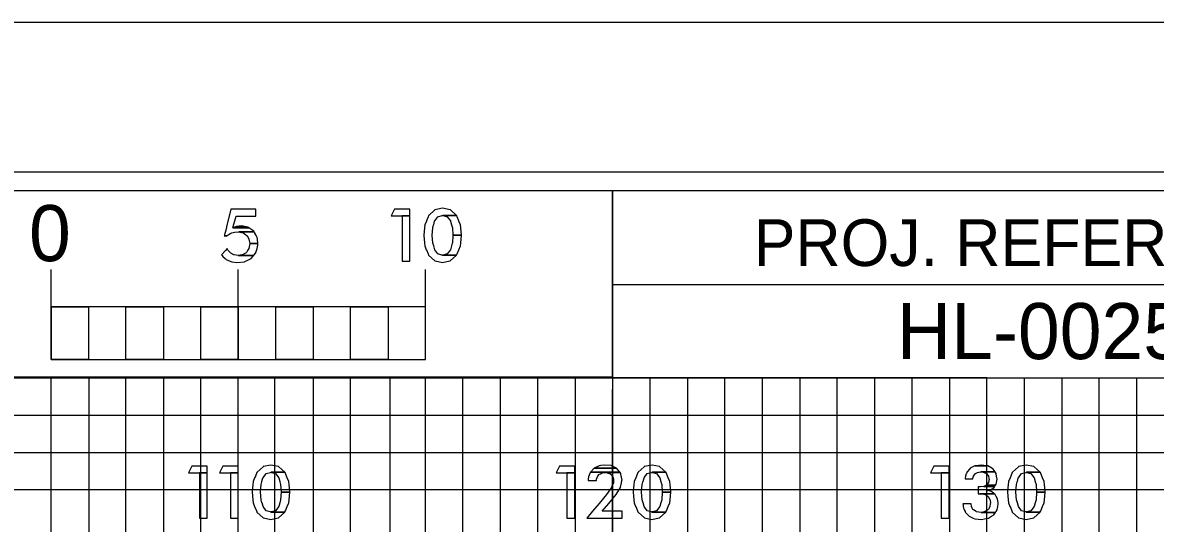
# Model space of a CAD drawing. Extents: x -13 to 323, y -5 to 1431.
# Drawn here: x 264.24 to 294.5, y 1081.11 to 1094.5 of the extents above; entities that cross this region are included whole.
import ezdxf

# ---------------------------------------------------------------- set-up
doc = ezdxf.new("R2010")
doc.units = 0
for name, color, linetype in [('Prop XS Bar Scale Labels', 7, 'Continuous'), ('Prop XS Offset Labels', 7, 'Continuous'), ('Prop XS Project Number', 7, 'Continuous'), ('Sheet Cross Section CELL', 7, 'Continuous'), ('Sheet Cross Section Grid Major CELL', 7, 'Continuous'), ('Sheet Cross Section Grid Middle CELL', 7, 'Continuous'), ('Sheet Cross Section Grid Minor 1 CELL', 7, 'Continuous'), ('Sheet Cross Section Grid Minor 2 CELL', 7, 'Continuous'), ('Sheet Cross Section Scale CELL', 7, 'Continuous'), ('Sheet Cutting Line CELL', 7, 'Continuous'), ('Sheet DOT Grid CELL', 7, 'Continuous'), ('Sheet Plot Border Inside CELL', 7, 'Continuous'), ('Sheet Plot Border Outside CELL', 7, 'Continuous')]:
    doc.layers.add(name, color=color, linetype=linetype)

msp = doc.modelspace()

# ---------------------------------------------------------------- linework, layer by layer
at = {"layer": 'Prop XS Bar Scale Labels'}
for points in [[(269.63, 1088.81), (269.627, 1088.798), (269.698, 1088.798), (269.711, 1088.81), (269.727, 1088.824), (269.798, 1088.867), (269.83, 1088.877), (269.9, 1088.899), (270.014, 1088.905), (270.422, 1088.905), (270.414, 1088.92), (270.28, 1089.015), (269.858, 1089.015), (269.861, 1089.028), (269.861, 1089.028), (269.866, 1089.048), (269.941, 1089.326), (270.466, 1089.326), (270.466, 1089.511), (269.803, 1089.511), (269.757, 1089.326), (269.689, 1089.048), (269.684, 1089.028), (269.681, 1089.015), (269.658, 1088.92), (269.654, 1088.905), (269.652, 1088.899), (269.647, 1088.877), (269.644, 1088.867), (269.634, 1088.824)], [(274.174, 1089.511), (274.085, 1089.329), (274.583, 1089.329), (274.583, 1089.511)], [(275.258, 1088.125), (275.457, 1088.084), (275.652, 1088.125), (275.663, 1088.127), (275.828, 1088.279), (275.454, 1088.279), (275.445, 1088.281), (275.44, 1088.283), (275.335, 1088.312), (275.248, 1088.425), (275.248, 1088.426), (275.248, 1088.426), (275.22, 1088.527), (275.22, 1088.529), (275.2, 1088.602), (275.198, 1088.606), (275.181, 1088.809), (275.181, 1088.811), (275.181, 1088.813), (275.198, 1089.015), (275.219, 1089.092), (275.22, 1089.094), (275.246, 1089.192), (275.247, 1089.195), (275.335, 1089.31), (275.448, 1089.339), (275.452, 1089.34), (275.462, 1089.343), (275.832, 1089.343), (275.669, 1089.492), (275.66, 1089.494), (275.46, 1089.538), (275.46, 1089.538), (275.252, 1089.494), (275.25, 1089.492), (275.088, 1089.343), (275.085, 1089.34), (275.084, 1089.339), (275.072, 1089.31), (275.025, 1089.195), (275.024, 1089.192), (274.983, 1089.094), (274.983, 1089.092), (274.975, 1089.015), (274.954, 1088.813), (274.953, 1088.811), (274.954, 1088.809), (274.974, 1088.606), (274.974, 1088.602), (274.982, 1088.529), (274.982, 1088.527), (275.023, 1088.426), (275.024, 1088.425), (275.07, 1088.312), (275.082, 1088.283), (275.082, 1088.281), (275.085, 1088.279), (275.255, 1088.127)], [(274.374, 1089.329), (274.374, 1088.12), (274.583, 1088.12), (274.583, 1089.329)], [(275.719, 1089.015), (275.735, 1088.813), (275.962, 1088.813), (275.942, 1089.015), (275.935, 1089.092), (275.934, 1089.094), (275.934, 1089.094), (275.895, 1089.192), (275.895, 1089.192), (275.893, 1089.195), (275.848, 1089.31), (275.847, 1089.31), (275.835, 1089.339), (275.835, 1089.34), (275.832, 1089.343), (275.462, 1089.343), (275.472, 1089.34), (275.475, 1089.339), (275.582, 1089.31), (275.669, 1089.195), (275.672, 1089.192), (275.698, 1089.094), (275.698, 1089.092)], [(269.627, 1088.798), (269.685, 1088.786), (269.698, 1088.798)], [(269.895, 1089.028), (269.858, 1089.015), (270.28, 1089.015), (270.262, 1089.028), (270.164, 1089.048), (269.953, 1089.048)], [(270.091, 1089.062), (269.953, 1089.048), (270.164, 1089.048), (270.091, 1089.062)], [(270.286, 1088.711), (270.308, 1088.591), (270.521, 1088.591), (270.51, 1088.711), (270.51, 1088.711), (270.507, 1088.751), (270.487, 1088.786), (270.481, 1088.798), (270.475, 1088.81), (270.467, 1088.824), (270.443, 1088.867), (270.438, 1088.877), (270.426, 1088.899), (270.422, 1088.905), (270.014, 1088.905), (270.041, 1088.899), (270.132, 1088.877), (270.146, 1088.867), (270.206, 1088.824), (270.227, 1088.81), (270.234, 1088.798), (270.241, 1088.786), (270.262, 1088.751)], [(275.465, 1088.281), (275.454, 1088.279), (275.828, 1088.279), (275.831, 1088.281), (275.833, 1088.283), (275.845, 1088.312), (275.892, 1088.425), (275.892, 1088.426), (275.934, 1088.527), (275.935, 1088.529), (275.942, 1088.602), (275.942, 1088.606), (275.962, 1088.809), (275.963, 1088.811), (275.962, 1088.813), (275.735, 1088.813), (275.735, 1088.811), (275.735, 1088.809), (275.719, 1088.606), (275.718, 1088.602), (275.699, 1088.529), (275.698, 1088.527), (275.671, 1088.426), (275.67, 1088.425), (275.582, 1088.312), (275.47, 1088.283)], [(270.103, 1088.288), (269.996, 1088.269), (270.408, 1088.269), (270.423, 1088.288), (270.424, 1088.289), (270.425, 1088.29), (270.425, 1088.29), (270.462, 1088.336), (270.471, 1088.347), (270.473, 1088.353), (270.487, 1088.405), (270.502, 1088.46), (270.525, 1088.544), (270.521, 1088.591), (270.308, 1088.591), (270.3, 1088.544), (270.286, 1088.46), (270.25, 1088.405), (270.217, 1088.353), (270.207, 1088.347), (270.19, 1088.336), (270.116, 1088.29), (270.108, 1088.289)], [(269.829, 1088.103), (269.965, 1088.084), (270.163, 1088.103), (270.171, 1088.107), (270.294, 1088.167), (270.294, 1088.167), (270.344, 1088.191), (270.388, 1088.245), (270.408, 1088.269), (269.996, 1088.269), (269.887, 1088.288), (269.885, 1088.289), (269.882, 1088.29), (269.799, 1088.336), (269.789, 1088.347), (269.783, 1088.353), (269.783, 1088.353), (269.733, 1088.405), (269.7, 1088.455), (269.7, 1088.455), (269.655, 1088.405), (269.608, 1088.353), (269.602, 1088.347), (269.593, 1088.336), (269.551, 1088.29), (269.55, 1088.289), (269.551, 1088.288), (269.566, 1088.269), (269.585, 1088.245), (269.649, 1088.191), (269.677, 1088.167), (269.801, 1088.107)]]:
    msp.add_lwpolyline(points, close=True, dxfattribs=at)
at = {"layer": 'Prop XS Offset Labels'}
for points in [[(268.76, 1082.641), (268.671, 1082.459), (269.17, 1082.459), (269.17, 1082.641)], [(268.961, 1082.459), (268.961, 1081.25), (269.17, 1081.25), (269.17, 1082.459)], [(269.587, 1082.641), (269.498, 1082.459), (269.997, 1082.459), (269.997, 1082.641)], [(269.788, 1082.459), (269.788, 1081.25), (269.997, 1081.25), (269.997, 1082.459)], [(270.672, 1081.255), (270.871, 1081.214), (271.066, 1081.255), (271.077, 1081.257), (271.242, 1081.409), (270.868, 1081.409), (270.858, 1081.411), (270.853, 1081.413), (270.749, 1081.442), (270.662, 1081.555), (270.661, 1081.556), (270.661, 1081.556), (270.634, 1081.657), (270.633, 1081.659), (270.613, 1081.732), (270.612, 1081.736), (270.594, 1081.939), (270.594, 1081.941), (270.595, 1081.943), (270.612, 1082.145), (270.633, 1082.222), (270.633, 1082.224), (270.66, 1082.322), (270.661, 1082.325), (270.749, 1082.44), (270.862, 1082.469), (270.865, 1082.47), (270.876, 1082.473), (271.246, 1082.473), (271.082, 1082.622), (271.074, 1082.624), (270.873, 1082.668), (270.873, 1082.668), (270.665, 1082.624), (270.663, 1082.622), (270.502, 1082.473), (270.499, 1082.47), (270.498, 1082.469), (270.486, 1082.44), (270.439, 1082.325), (270.437, 1082.322), (270.397, 1082.224), (270.397, 1082.222), (270.389, 1082.145), (270.367, 1081.943), (270.367, 1081.941), (270.367, 1081.939), (270.387, 1081.736), (270.388, 1081.732), (270.395, 1081.659), (270.396, 1081.657), (270.437, 1081.556), (270.437, 1081.555), (270.483, 1081.442), (270.495, 1081.413), (270.496, 1081.411), (270.499, 1081.409), (270.669, 1081.257)], [(271.132, 1082.145), (271.149, 1081.943), (271.376, 1081.943), (271.356, 1082.145), (271.349, 1082.222), (271.348, 1082.224), (271.348, 1082.224), (271.308, 1082.322), (271.308, 1082.322), (271.307, 1082.325), (271.261, 1082.44), (271.261, 1082.44), (271.249, 1082.469), (271.249, 1082.47), (271.246, 1082.473), (270.876, 1082.473), (270.885, 1082.47), (270.889, 1082.469), (270.995, 1082.44), (271.083, 1082.325), (271.085, 1082.322), (271.111, 1082.224), (271.112, 1082.222)], [(278.581, 1082.641), (278.492, 1082.459), (278.99, 1082.459), (278.99, 1082.641)], [(278.781, 1082.459), (278.781, 1081.25), (278.99, 1081.25), (278.99, 1082.459)], [(279.465, 1081.432), (279.313, 1081.25), (280.253, 1081.25), (280.253, 1081.432), (279.719, 1081.432), (279.898, 1081.638), (280.095, 1081.879), (280.097, 1081.881), (280.208, 1082.069), (280.208, 1082.069), (280.211, 1082.074), (280.235, 1082.193), (280.247, 1082.254), (280.252, 1082.279), (280.25, 1082.29), (280.249, 1082.293), (280.236, 1082.354), (280.235, 1082.36), (280.233, 1082.37), (280.222, 1082.421), (280.222, 1082.421), (280.219, 1082.435), (280.213, 1082.461), (280.211, 1082.464), (280.207, 1082.468), (279.839, 1082.468), (279.85, 1082.464), (279.858, 1082.461), (279.933, 1082.435), (279.946, 1082.421), (279.996, 1082.37), (280, 1082.36), (280.002, 1082.354), (280.022, 1082.293), (280.022, 1082.29), (280.022, 1082.279), (280.022, 1082.254), (280.021, 1082.193), (279.973, 1082.074), (279.972, 1082.069), (279.839, 1081.881), (279.838, 1081.879), (279.637, 1081.638)], [(279.349, 1082.279), (279.347, 1082.254), (279.567, 1082.254), (279.569, 1082.279), (279.57, 1082.29), (279.571, 1082.293), (279.593, 1082.354), (279.598, 1082.36), (279.606, 1082.37), (279.645, 1082.421), (279.673, 1082.435), (279.725, 1082.461), (279.73, 1082.464), (279.839, 1082.468), (280.207, 1082.468), (280.197, 1082.479), (279.41, 1082.479), (279.405, 1082.468), (279.403, 1082.464), (279.402, 1082.461), (279.39, 1082.435), (279.384, 1082.421), (279.361, 1082.37), (279.357, 1082.36), (279.356, 1082.354), (279.35, 1082.293), (279.35, 1082.29)], [(279.507, 1082.583), (279.41, 1082.479), (280.197, 1082.479), (280.108, 1082.583)], [(279.512, 1082.585), (279.507, 1082.583), (280.108, 1082.583), (280.106, 1082.585), (279.974, 1082.645), (279.958, 1082.652), (279.794, 1082.668), (279.794, 1082.668), (279.685, 1082.652), (279.637, 1082.645)], [(280.851, 1081.255), (281.051, 1081.214), (281.245, 1081.255), (281.256, 1081.257), (281.422, 1081.409), (281.048, 1081.409), (281.038, 1081.411), (281.033, 1081.413), (280.928, 1081.442), (280.841, 1081.555), (280.841, 1081.556), (280.841, 1081.556), (280.813, 1081.657), (280.813, 1081.659), (280.793, 1081.732), (280.792, 1081.736), (280.774, 1081.939), (280.774, 1081.941), (280.774, 1081.943), (280.792, 1082.145), (280.812, 1082.222), (280.813, 1082.224), (280.839, 1082.322), (280.84, 1082.325), (280.928, 1082.44), (281.041, 1082.469), (281.045, 1082.47), (281.055, 1082.473), (281.425, 1082.473), (281.262, 1082.622), (281.254, 1082.624), (281.053, 1082.668), (281.053, 1082.668), (280.845, 1082.624), (280.843, 1082.622), (280.681, 1082.473), (280.678, 1082.47), (280.678, 1082.469), (280.665, 1082.44), (280.618, 1082.325), (280.617, 1082.322), (280.577, 1082.224), (280.576, 1082.222), (280.568, 1082.145), (280.547, 1081.943), (280.547, 1081.941), (280.547, 1081.939), (280.567, 1081.736), (280.567, 1081.732), (280.575, 1081.659), (280.575, 1081.657), (280.616, 1081.556), (280.617, 1081.555), (280.663, 1081.442), (280.675, 1081.413), (280.676, 1081.411), (280.679, 1081.409), (280.848, 1081.257)], [(281.312, 1082.145), (281.328, 1081.943), (281.555, 1081.943), (281.536, 1082.145), (281.528, 1082.222), (281.528, 1082.224), (281.527, 1082.224), (281.488, 1082.322), (281.488, 1082.322), (281.487, 1082.325), (281.441, 1082.44), (281.44, 1082.44), (281.429, 1082.469), (281.428, 1082.47), (281.425, 1082.473), (281.055, 1082.473), (281.065, 1082.47), (281.068, 1082.469), (281.175, 1082.44), (281.262, 1082.325), (281.265, 1082.322), (281.291, 1082.224), (281.291, 1082.222)], [(288.581, 1082.641), (288.492, 1082.459), (288.99, 1082.459), (288.99, 1082.641)], [(288.781, 1082.459), (288.781, 1081.25), (288.99, 1081.25), (288.99, 1082.459)], [(289.42, 1082.315), (289.418, 1082.297), (289.626, 1082.297), (289.627, 1082.315), (289.639, 1082.365), (289.64, 1082.372), (289.641, 1082.373), (289.683, 1082.433), (289.688, 1082.436), (289.696, 1082.44), (289.748, 1082.47), (289.785, 1082.476), (289.795, 1082.478), (289.835, 1082.485), (290.217, 1082.485), (290.165, 1082.561), (290.129, 1082.582), (290.128, 1082.582), (290.022, 1082.644), (289.982, 1082.65), (289.69, 1082.65), (289.678, 1082.644), (289.553, 1082.582), (289.536, 1082.561), (289.471, 1082.485), (289.466, 1082.478), (289.465, 1082.476), (289.463, 1082.47), (289.452, 1082.44), (289.45, 1082.436), (289.449, 1082.433), (289.428, 1082.373), (289.427, 1082.372), (289.425, 1082.365)], [(289.853, 1082.668), (289.69, 1082.65), (289.982, 1082.65)], [(290.007, 1082.155), (289.988, 1082.131), (290.23, 1082.131), (290.246, 1082.155), (290.254, 1082.201), (290.271, 1082.289), (290.272, 1082.295), (290.272, 1082.297), (290.269, 1082.315), (290.26, 1082.365), (290.259, 1082.372), (290.259, 1082.373), (290.259, 1082.373), (290.249, 1082.433), (290.248, 1082.436), (290.248, 1082.44), (290.227, 1082.47), (290.223, 1082.476), (290.222, 1082.478), (290.217, 1082.485), (289.835, 1082.485), (289.901, 1082.478), (289.919, 1082.476), (289.931, 1082.47), (289.986, 1082.44), (289.995, 1082.436), (289.997, 1082.433), (290.04, 1082.373), (290.04, 1082.372), (290.042, 1082.365), (290.051, 1082.315), (290.054, 1082.297), (290.055, 1082.295), (290.056, 1082.289), (290.041, 1082.201)], [(290.851, 1081.255), (291.051, 1081.214), (291.245, 1081.255), (291.256, 1081.257), (291.422, 1081.409), (291.048, 1081.409), (291.038, 1081.411), (291.033, 1081.413), (290.928, 1081.442), (290.841, 1081.555), (290.841, 1081.556), (290.841, 1081.556), (290.813, 1081.657), (290.813, 1081.659), (290.793, 1081.732), (290.792, 1081.736), (290.774, 1081.939), (290.774, 1081.941), (290.774, 1081.943), (290.792, 1082.145), (290.812, 1082.222), (290.813, 1082.224), (290.839, 1082.322), (290.84, 1082.325), (290.928, 1082.44), (291.041, 1082.469), (291.045, 1082.47), (291.055, 1082.473), (291.425, 1082.473), (291.262, 1082.622), (291.254, 1082.624), (291.053, 1082.668), (291.053, 1082.668), (290.845, 1082.624), (290.843, 1082.622), (290.681, 1082.473), (290.678, 1082.47), (290.678, 1082.469), (290.665, 1082.44), (290.618, 1082.325), (290.617, 1082.322), (290.577, 1082.224), (290.576, 1082.222), (290.568, 1082.145), (290.547, 1081.943), (290.547, 1081.941), (290.547, 1081.939), (290.567, 1081.736), (290.567, 1081.732), (290.575, 1081.659), (290.575, 1081.657), (290.616, 1081.556), (290.617, 1081.555), (290.663, 1081.442), (290.675, 1081.413), (290.676, 1081.411), (290.679, 1081.409), (290.848, 1081.257)], [(291.312, 1082.145), (291.328, 1081.943), (291.555, 1081.943), (291.536, 1082.145), (291.528, 1082.222), (291.528, 1082.224), (291.527, 1082.224), (291.488, 1082.322), (291.488, 1082.322), (291.487, 1082.325), (291.441, 1082.44), (291.44, 1082.44), (291.429, 1082.469), (291.428, 1082.47), (291.425, 1082.473), (291.055, 1082.473), (291.065, 1082.47), (291.068, 1082.469), (291.175, 1082.44), (291.262, 1082.325), (291.265, 1082.322), (291.291, 1082.224), (291.291, 1082.222)], [(289.988, 1082.131), (289.915, 1082.095), (290.207, 1082.095), (290.23, 1082.131)], [(270.878, 1081.411), (270.868, 1081.409), (271.242, 1081.409), (271.245, 1081.411), (271.247, 1081.413), (271.259, 1081.442), (271.305, 1081.555), (271.306, 1081.556), (271.348, 1081.657), (271.348, 1081.659), (271.355, 1081.732), (271.356, 1081.736), (271.376, 1081.939), (271.376, 1081.941), (271.376, 1081.943), (271.149, 1081.943), (271.149, 1081.941), (271.148, 1081.939), (271.132, 1081.736), (271.132, 1081.732), (271.112, 1081.659), (271.112, 1081.657), (271.085, 1081.556), (271.084, 1081.555), (270.995, 1081.442), (270.883, 1081.413)], [(281.058, 1081.411), (281.048, 1081.409), (281.422, 1081.409), (281.425, 1081.411), (281.426, 1081.413), (281.438, 1081.442), (281.485, 1081.555), (281.485, 1081.556), (281.527, 1081.657), (281.528, 1081.659), (281.535, 1081.732), (281.535, 1081.736), (281.555, 1081.939), (281.556, 1081.941), (281.555, 1081.943), (281.328, 1081.943), (281.328, 1081.941), (281.328, 1081.939), (281.312, 1081.736), (281.312, 1081.732), (281.292, 1081.659), (281.291, 1081.657), (281.264, 1081.556), (281.263, 1081.555), (281.175, 1081.442), (281.063, 1081.413)], [(289.765, 1081.956), (289.765, 1081.9), (290.194, 1081.9), (290.119, 1081.956), (290.029, 1081.983), (290.095, 1082), (290.181, 1082.053), (290.2, 1082.084), (290.201, 1082.085), (290.207, 1082.095), (289.915, 1082.095), (289.83, 1082.085), (289.765, 1082.084), (289.765, 1082.053), (289.765, 1082), (289.765, 1081.983)], [(289.925, 1081.416), (289.849, 1081.401), (290.229, 1081.401), (290.239, 1081.416), (290.243, 1081.423), (290.243, 1081.423), (290.275, 1081.471), (290.277, 1081.479), (290.277, 1081.482), (290.283, 1081.516), (290.292, 1081.562), (290.293, 1081.567), (290.303, 1081.62), (290.297, 1081.662), (290.285, 1081.751), (290.283, 1081.763), (290.25, 1081.826), (290.223, 1081.877), (290.222, 1081.88), (290.197, 1081.898), (290.194, 1081.9), (289.81, 1081.9), (289.877, 1081.898), (289.951, 1081.88), (289.963, 1081.877), (290.033, 1081.826), (290.07, 1081.763), (290.077, 1081.751), (290.092, 1081.662), (290.088, 1081.62), (290.082, 1081.567), (290.08, 1081.562), (290.057, 1081.516), (290.039, 1081.482), (290.035, 1081.479), (290.025, 1081.471), (289.957, 1081.423)], [(291.058, 1081.411), (291.048, 1081.409), (291.422, 1081.409), (291.425, 1081.411), (291.426, 1081.413), (291.438, 1081.442), (291.485, 1081.555), (291.485, 1081.556), (291.527, 1081.657), (291.528, 1081.659), (291.535, 1081.732), (291.535, 1081.736), (291.555, 1081.939), (291.556, 1081.941), (291.555, 1081.943), (291.328, 1081.943), (291.328, 1081.941), (291.328, 1081.939), (291.312, 1081.736), (291.312, 1081.732), (291.292, 1081.659), (291.291, 1081.657), (291.264, 1081.556), (291.263, 1081.555), (291.175, 1081.442), (291.063, 1081.413)], [(289.677, 1081.229), (289.854, 1081.214), (289.936, 1081.229), (290.042, 1081.248), (290.123, 1081.297), (290.187, 1081.336), (290.228, 1081.399), (290.229, 1081.401), (289.849, 1081.401), (289.72, 1081.416), (289.711, 1081.423), (289.639, 1081.471), (289.628, 1081.479), (289.626, 1081.482), (289.608, 1081.516), (289.584, 1081.562), (289.584, 1081.567), (289.58, 1081.62), (289.58, 1081.625), (289.361, 1081.625), (289.362, 1081.62), (289.369, 1081.567), (289.37, 1081.562), (289.377, 1081.516), (289.391, 1081.482), (289.392, 1081.479), (289.395, 1081.471), (289.415, 1081.423), (289.418, 1081.416), (289.425, 1081.401), (289.426, 1081.399), (289.49, 1081.336), (289.53, 1081.297), (289.635, 1081.248)]]:
    msp.add_lwpolyline(points, close=True, dxfattribs=at)
at = {"layer": 'Sheet Cross Section CELL'}
for p, q in [((280, 1087.5), (280, 1085)), ((320, 1087.49), (280, 1087.49)), ((280, 1085), (320, 1085))]:
    msp.add_line(p, q, dxfattribs=at)
for points in [[(320, 1090), (0, 1090), (0, 880), (320, 880)], [(280, 1090), (260, 1090), (260, 1085.03), (280, 1085.03)], [(320, 1090), (280, 1090), (280, 1085), (320, 1085)]]:
    msp.add_lwpolyline(points, close=True, dxfattribs=at)
at = {"layer": 'Sheet Cross Section Grid Major CELL'}
for p, q in [((270, 880), (270, 1085)), ((290, 1085), (280, 1085)), ((280, 1085), (280, 880)), ((290, 880), (290, 1085))]:
    msp.add_line(p, q, dxfattribs=at)
at = {"layer": 'Sheet Cross Section Grid Middle CELL'}
for points in [[(255, 880), (255, 1090), (259.93, 1090), (260, 1090), (260, 1085), (264.99, 1085), (264.99, 880)], [(0, 1085), (275, 1085)], [(275, 880), (275, 1085), (285, 1085), (285, 880)]]:
    msp.add_lwpolyline(points, dxfattribs=at)
at = {"layer": 'Sheet Cross Section Grid Minor 1 CELL'}
msp.add_line((0, 1084), (320, 1084), dxfattribs=at)
msp.add_lwpolyline([(0, 1083), (270, 1083), (320, 1083), (320, 1082), (0, 1082)], dxfattribs=at)
at = {"layer": 'Sheet Cross Section Grid Minor 2 CELL'}
for p, q in [((267, 1085), (266.01, 1085)), ((266.01, 1085), (266.01, 880)), ((267, 880), (267, 1085)), ((269, 1085), (268, 1085)), ((268, 1085), (268, 880)), ((269, 880), (269, 1085))]:
    msp.add_line(p, q, dxfattribs=at)
for points in [[(270, 880), (270.98, 880), (270.98, 1085), (272, 1085), (272, 880)], [(272, 880), (273, 880), (273, 1085), (274.05, 1085), (274.05, 880)], [(275, 880), (276, 880), (276, 1085), (277, 1085), (277, 880)], [(277, 880), (278, 880), (278, 1085), (279, 1085), (279, 880)], [(280, 880), (281, 880), (281, 1085), (282, 1085), (282, 880)], [(282, 880), (283, 880), (283, 1085), (284, 1085), (284, 880)], [(285, 880), (286, 880), (286, 1085), (287, 1085), (287, 880)], [(287, 880), (288, 880), (288, 1085), (289, 1085), (289, 880)], [(290, 880), (291, 880), (291, 1085), (292, 1085), (292, 880)], [(292, 880), (293, 880), (293, 1085), (294, 1085), (294, 880)]]:
    msp.add_lwpolyline(points, dxfattribs=at)
at = {"layer": 'Sheet Cross Section Scale CELL'}
for p, q in [((265, 1085.49), (265, 1087.9)), ((265, 1086.9), (265, 1087.9)), ((270, 1085.49), (270, 1087.9)), ((275, 1085.49), (275, 1087.9)), ((275, 1086.9), (275, 1087.9))]:
    msp.add_line(p, q, dxfattribs=at)
for points in [[(275, 1086.9), (265, 1086.9), (265, 1085.49), (275, 1085.49)], [(265, 1086.9), (266, 1086.9), (266, 1085.49), (265, 1085.49)], [(267, 1086.9), (268, 1086.9), (268, 1085.49), (267, 1085.49)], [(269, 1086.9), (270, 1086.9), (270, 1085.49), (269, 1085.49)], [(271, 1086.9), (272, 1086.9), (272, 1085.49), (271, 1085.49)], [(273, 1086.9), (274, 1086.9), (274, 1085.49), (273, 1085.49)]]:
    msp.add_lwpolyline(points, close=True, dxfattribs=at)
at = {"layer": 'Sheet Cutting Line CELL'}
msp.add_line((323.3, 1094.5), (-13.4, 1094.5), dxfattribs=at)
at = {"layer": 'Sheet DOT Grid CELL'}
for p, q in [((270, 880), (270, 1084.687)), ((280, 880), (280, 1084.687)), ((290, 880), (290, 1084.687))]:
    msp.add_line(p, q, dxfattribs=at)
at = {"layer": 'Sheet Plot Border Inside CELL'}
msp.add_lwpolyline([(-10.8, 879.5), (322.4, 879.5), (322.4, 1090.5), (-10.8, 1090.5)], close=True, dxfattribs=at)
at = {"layer": 'Sheet Plot Border Outside CELL'}
msp.add_lwpolyline([(-13.4, 875.5), (323.3, 875.5), (323.3, 1094.5), (-13.4, 1094.5)], close=True, dxfattribs=at)

# ---------------------------------------------------------------- texts
at = {"layer": 'Prop XS Project Number'}
msp.add_text('HL-0025', height=1.5, dxfattribs=at).set_placement((287.598, 1085.5))
at = {"layer": 'Sheet Cross Section CELL'}
msp.add_text('PROJ. REFERENCE NO.', height=1.24998, dxfattribs=at).set_placement((283.77, 1087.99))
at = {"layer": 'Sheet Cross Section Scale CELL'}
msp.add_text('0', height=1.5, dxfattribs=at).set_placement((264.41, 1088.12))

doc.saveas('drawing.dxf')
